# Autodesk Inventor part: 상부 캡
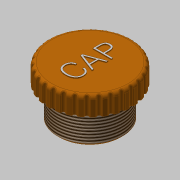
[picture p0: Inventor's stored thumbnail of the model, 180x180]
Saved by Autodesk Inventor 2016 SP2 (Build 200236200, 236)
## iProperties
Created: 2016-09
Part Number: 상부 캡
Material: ABS 플라스틱
Document SubType Name: Modeling
Designer: mduedu
Density: 1.06 g/cm^3
Mass: 28.3104 g
Surface Area: 72.7445 cm^2
Volume: 26.7079 cm^3
Appearance: 주황색
Author: mduedu
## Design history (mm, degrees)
sketch "스케치1"
  geometry: C1 r 22.5 at (0, 0); 1 further point
  constraints: 1 centre point, 1 coincident
  dimensions: "d0" = 45 diameter of C1
extrude "돌출1" new body sketch "스케치1" distance "d1" = 10; taper "d2" = 0 deg
fillet "모깎기1" dims "d11" = 2
sketch "스케치4"
  geometry: C1 r 17.5 at (0, 0); 1 further point
  constraints: 1 centre point, 1 coincident
  dimensions: "d14" = 35 diameter of C1
extrude "돌출4" join sketch "스케치4" distance "d15" = 17; taper "d16" = 0 deg
sketch "스케치5"
  geometry: C1 r 12.5 at (0, 0); 1 further point
  constraints: 1 centre point, 1 coincident
  dimensions: "d17" = 25 diameter of C1
extrude "돌출5" cut sketch "스케치5" distance "d18" = 10; taper "d19" = 0 deg
fillet "모깎기4" dims "d20" = 3
sketch "스케치6"
  geometry: L1 (0, 22.5)-(0, -22.5) reference; L2 (0, 17.5)-(-1, 17.5); L3 (-1, 17.5)-(-1, 16.5); L4 (-1, 16.5)-(0, 16.5); L5 (0, 16.5)-(0, 17.5); L6 (0, 17.5)-(-17, 17.5) reference; L7 (-20.4, 0)-(3.4, 0) reference; 1 further point
  constraints: 8 end point, 2 parallel, 1 collinear, 1 horizontal, 1 perpendicular, 1 point on line
  dimensions: "d26" = 1 distance of L2.start L2.end; "d28" = 1 distance of L2.end L3.end
revolve "회전1" sketch "스케치6" stored, may be unused: angle "d29" = 90 deg
feature "스레드1" dims "d21" = 10, "d22" = 0
chamfer "모따기1" distance "d23" = 1; stored, may be unused: second distance "d24" = 2, angle "d25" = 45 deg
chamfer "모따기2" distance "d30" = 1; stored, may be unused: second distance "d31" = 2, angle "d32" = 45 deg
sketch "스케치7"
  geometry: C1 r 1 at (0, 22.5); 2 further points
  constraints: 2 vertical alignment, 1 centre point, 1 other
  dimensions: "d33" = 2 diameter of C1
extrude "돌출6" cut sketch "스케치7" stored distance "d35" = 10; taper "d36" = 0 deg
fillet "모깎기5" dims "d37" = 0.5
sketch "스케치8"
  geometry: 2 further points
  constraints: 1 coincident, 1 other
feature "엠보싱1" sketch "스케치8" dims "d0" = 45, "d41" = 0.5, "d42" = 0
node "솔리드1"
pattern_circular "원형 패턴1" dims angle "d39" = 360 deg
